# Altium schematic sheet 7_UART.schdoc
size 401 x 147 mm
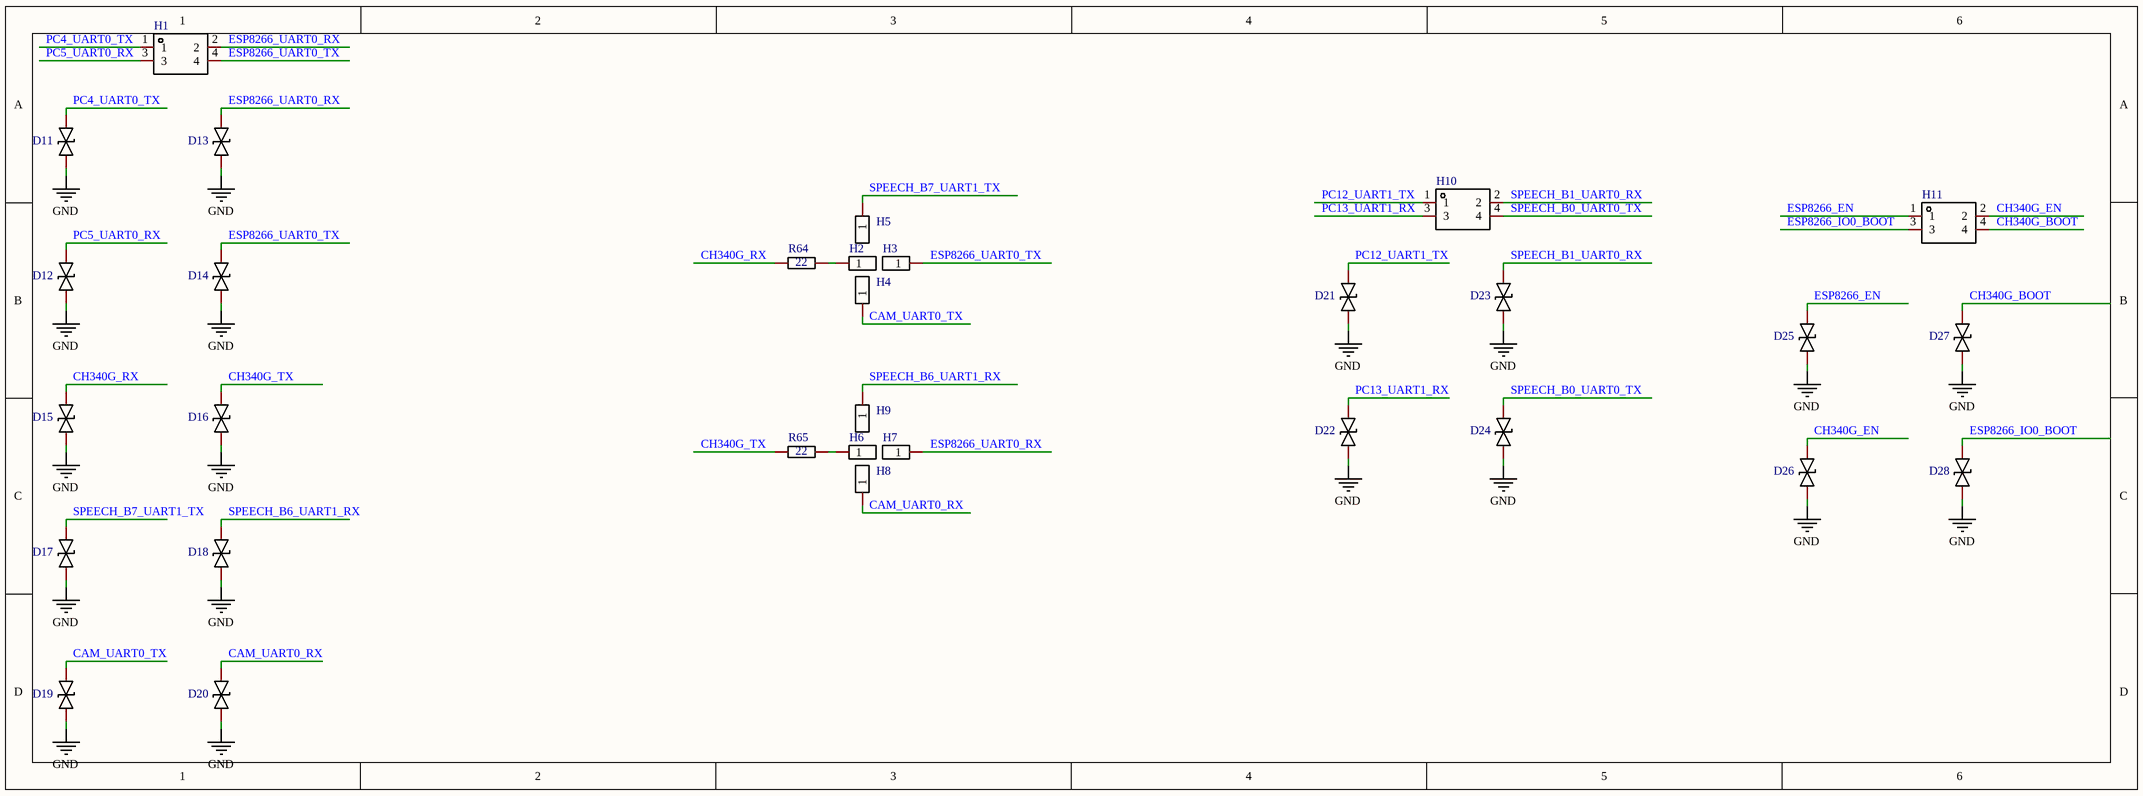
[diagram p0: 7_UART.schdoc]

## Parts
D11  SD03C  [SOD-323_L1.8-W1.3-LS2.5-BI]  (value not drawn)
D12  SD03C  [SOD-323_L1.8-W1.3-LS2.5-BI]  (value not drawn)
D13  SD03C  [SOD-323_L1.8-W1.3-LS2.5-BI]  (value not drawn)
D14  SD03C  [SOD-323_L1.8-W1.3-LS2.5-BI]  (value not drawn)
D15  SD03C  [SOD-323_L1.8-W1.3-LS2.5-BI]  (value not drawn)
D16  SD03C  [SOD-323_L1.8-W1.3-LS2.5-BI]  (value not drawn)
D17  SD03C  [SOD-323_L1.8-W1.3-LS2.5-BI]  (value not drawn)
D18  SD03C  [SOD-323_L1.8-W1.3-LS2.5-BI]  (value not drawn)
D19  SD03C  [SOD-323_L1.8-W1.3-LS2.5-BI]  (value not drawn)
D20  SD03C  [SOD-323_L1.8-W1.3-LS2.5-BI]  (value not drawn)
D21  SD03C  [SOD-323_L1.8-W1.3-LS2.5-BI]  (value not drawn)
D22  SD03C  [SOD-323_L1.8-W1.3-LS2.5-BI]  (value not drawn)
D23  SD03C  [SOD-323_L1.8-W1.3-LS2.5-BI]  (value not drawn)
D24  SD03C  [SOD-323_L1.8-W1.3-LS2.5-BI]  (value not drawn)
D25  SD03C  [SOD-323_L1.8-W1.3-LS2.5-BI]  (value not drawn)
D26  SD03C  [SOD-323_L1.8-W1.3-LS2.5-BI]  (value not drawn)
D27  SD03C  [SOD-323_L1.8-W1.3-LS2.5-BI]  (value not drawn)
D28  SD03C  [SOD-323_L1.8-W1.3-LS2.5-BI]  (value not drawn)
H1  HDR-M_2.54_2x2  [HDR-TH_4P-P2.54-V-M-R2-C2-S2.54-1]  (value not drawn)
H2  HDR-M_2.54_1x1P  [HDR-TH_1P-V-M_XKB_X4611WV-01I-C28D40]  (value not drawn)
H3  HDR-M_2.54_1x1P  [HDR-TH_1P-V-M_XKB_X4611WV-01I-C28D40]  (value not drawn)
H4  HDR-M_2.54_1x1P  [HDR-TH_1P-V-M_XKB_X4611WV-01I-C28D40]  (value not drawn)
H5  HDR-M_2.54_1x1P  [HDR-TH_1P-V-M_XKB_X4611WV-01I-C28D40]  (value not drawn)
H6  HDR-M_2.54_1x1P  [HDR-TH_1P-V-M_XKB_X4611WV-01I-C28D40]  (value not drawn)
H7  HDR-M_2.54_1x1P  [HDR-TH_1P-V-M_XKB_X4611WV-01I-C28D40]  (value not drawn)
H8  HDR-M_2.54_1x1P  [HDR-TH_1P-V-M_XKB_X4611WV-01I-C28D40]  (value not drawn)
H9  HDR-M_2.54_1x1P  [HDR-TH_1P-V-M_XKB_X4611WV-01I-C28D40]  (value not drawn)
H10  HDR-M_2.54_2x2  [HDR-TH_4P-P2.54-V-M-R2-C2-S2.54-1]  (value not drawn)
H11  HDR-M_2.54_2x2  [HDR-TH_4P-P2.54-V-M-R2-C2-S2.54-1]  (value not drawn)
R64  22  [R0603]
R65  22  [R0603]

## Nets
GND: D11.2 D12.2 D13.2 D14.2 D15.2 D16.2 D17.2 D18.2 D19.2 D20.2 D21.2 D22.2 D23.2 D24.2 D25.2 D26.2 D27.2 D28.2
CAM_UART0_RX: D20.1 H8.1
CAM_UART0_TX: D19.1 H4.1
CH340G_BOOT: D27.1 H11.4
CH340G_EN: D26.1 H11.2
CH340G_RX: D15.1 R64.1
CH340G_TX: D16.1 R65.1
ESP8266_EN: D25.1 H11.1
ESP8266_IO0_BOOT: D28.1 H11.3
ESP8266_UART0_RX: D13.1 H1.2 H7.1
ESP8266_UART0_TX: D14.1 H1.4 H3.1
PC4_UART0_TX: D11.1 H1.1
PC5_UART0_RX: D12.1 H1.3
PC12_UART1_TX: D21.1 H10.1
PC13_UART1_RX: D22.1 H10.3
SPEECH_B0_UART0_TX: D24.1 H10.4
SPEECH_B1_UART0_RX: D23.1 H10.2
SPEECH_B6_UART1_RX: D18.1 H9.1
SPEECH_B7_UART1_TX: D17.1 H5.1
NetH2_1: H2.1 R64.2
NetH6_1: H6.1 R65.2

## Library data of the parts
D11-D28 = SD03C_C502532: 极性:双向;反向截止电压(Vrwm):3.3V;击穿电压(最小值):4V;峰值脉冲电流(Ipp)@10/1000μs:20A;最大钳位电压:16V;; Manufacturer: MDD; Add into BOM: yes; Polarity: 双向; Reverse Stand-Off Voltage (Vrwm): 3.3V; Breakdown Voltage (Min): 4V; Peak Pulse Current (Ipp)@10/1000μs: 20A; Maximum Clamping Voltage: 16V
H1 H10 H11 = HDR-M_2.54_2x2: Symbol: HDR-M-2.54_2x2; Convert to PCB: yes
H2-H9 = HDR-M_2.54_1x1P: Symbol: HDR_1x1; Convert to PCB: yes
R64 R65 = Res_0603: Symbol: 电阻; Convert to PCB: yes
